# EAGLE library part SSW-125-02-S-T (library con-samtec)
THROUGH-HOLE .025" SQ POST SOCKET Source: Samtec SSW.pdf
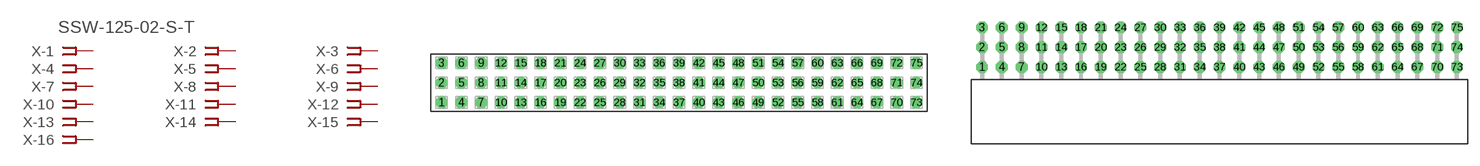
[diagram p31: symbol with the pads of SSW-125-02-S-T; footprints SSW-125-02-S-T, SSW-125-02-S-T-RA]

Designator prefix X; gates -1=FPINV -2=FPIN -3=FPIN -4=FPIN -5=FPIN -6=FPIN -7=FPIN -8=FPIN -9=FPIN -10=FPIN -11=FPIN -12=FPIN -13=FPIN -14=FPIN -15=FPIN -16=FPIN -17=FPIN -18=FPIN -19=FPIN -20=FPIN -21=FPIN -22=FPIN -23=FPIN -24=FPIN -25=FPIN -26=FPIN -27=FPIN -28=FPIN -29=FPIN -30=FPIN -31=FPIN -32=FPIN -33=FPIN -34=FPIN -35=FPIN -36=FPIN -37=FPIN -38=FPIN -39=FPIN -40=FPIN -41=FPIN -42=FPIN -43=FPIN -44=FPIN -45=FPIN -46=FPIN -47=FPIN -48=FPIN -49=FPIN -50=FPIN -51=FPIN -52=FPIN -53=FPIN -54=FPIN -55=FPIN -56=FPIN -57=FPIN -58=FPIN -59=FPIN -60=FPIN -61=FPIN -62=FPIN -63=FPIN -64=FPIN -65=FPIN -66=FPIN -67=FPIN -68=FPIN -69=FPIN -70=FPIN -71=FPIN -72=FPIN -73=FPIN -74=FPIN -75=FPIN

## SSW-125-02-S-T (MPN: SSW-125-02-S-T; OC_FARNELL: unknown; OC_NEWARK: 82P9300)  [SSW-125-02-S-T]
1  -1:1  pas
2  -2:1  pas
3  -3:1  pas
4  -4:1  pas
5  -5:1  pas
6  -6:1  pas
7  -7:1  pas
8  -8:1  pas
9  -9:1  pas
10  -10:1  pas
11  -11:1  pas
12  -12:1  pas
13  -13:1  pas
14  -14:1  pas
15  -15:1  pas
16  -16:1  pas
17  -17:1  pas
18  -18:1  pas
19  -19:1  pas
20  -20:1  pas
21  -21:1  pas
22  -22:1  pas
23  -23:1  pas
24  -24:1  pas
25  -25:1  pas
26  -26:1  pas
27  -27:1  pas
28  -28:1  pas
29  -29:1  pas
30  -30:1  pas
31  -31:1  pas
32  -32:1  pas
33  -33:1  pas
34  -34:1  pas
35  -35:1  pas
36  -36:1  pas
37  -37:1  pas
38  -38:1  pas
39  -39:1  pas
40  -40:1  pas
41  -41:1  pas
42  -42:1  pas
43  -43:1  pas
44  -44:1  pas
45  -45:1  pas
46  -46:1  pas
47  -47:1  pas
48  -48:1  pas
49  -49:1  pas
50  -50:1  pas
51  -51:1  pas
52  -52:1  pas
53  -53:1  pas
54  -54:1  pas
55  -55:1  pas
56  -56:1  pas
57  -57:1  pas
58  -58:1  pas
59  -59:1  pas
60  -60:1  pas
61  -61:1  pas
62  -62:1  pas
63  -63:1  pas
64  -64:1  pas
65  -65:1  pas
66  -66:1  pas
67  -67:1  pas
68  -68:1  pas
69  -69:1  pas
70  -70:1  pas
71  -71:1  pas
72  -72:1  pas
73  -73:1  pas
74  -74:1  pas
75  -75:1  pas

## SSW-125-02-S-TRA (MPN: SSW-125-02-S-T-RA; OC_FARNELL: unknown; OC_NEWARK: 82P9301)  [SSW-125-02-S-T-RA]
Pads as for SSW-125-02-S-T

## Footprint SSW-125-02-S-T (pad centres in mm)
THROUGH-HOLE .025" SQ POST SOCKET Source: Samtec SSW.pdf
drill 1 pad 1.5 octagon: 1 -30.48,-2.54; 2 -30.48,0; 3 -30.48,2.54; 4 -27.94,-2.54; 5 -27.94,0; 6 -27.94,2.54; 7 -25.4,-2.54; 8 -25.4,0; 9 -25.4,2.54; 10 -22.86,-2.54; 11 -22.86,0; 12 -22.86,2.54; 13 -20.32,-2.54; 14 -20.32,0; 15 -20.32,2.54; 16 -17.78,-2.54; 17 -17.78,0; 18 -17.78,2.54; 19 -15.24,-2.54; 20 -15.24,0; 21 -15.24,2.54; 22 -12.7,-2.54; 23 -12.7,0; 24 -12.7,2.54; 25 -10.16,-2.54; 26 -10.16,0; 27 -10.16,2.54; 28 -7.62,-2.54; 29 -7.62,0; 30 -7.62,2.54; 31 -5.08,-2.54; 32 -5.08,0; 33 -5.08,2.54; 34 -2.54,-2.54; 35 -2.54,0; 36 -2.54,2.54; 37 0,-2.54; 38 0,0; 39 0,2.54; 40 2.54,-2.54; 41 2.54,0; 42 2.54,2.54; 43 5.08,-2.54; 44 5.08,0; 45 5.08,2.54; 46 7.62,-2.54; 47 7.62,0; 48 7.62,2.54; 49 10.16,-2.54; 50 10.16,0; 51 10.16,2.54; 52 12.7,-2.54; 53 12.7,0; 54 12.7,2.54; 55 15.24,-2.54; 56 15.24,0; 57 15.24,2.54; 58 17.78,-2.54; 59 17.78,0; 60 17.78,2.54; 61 20.32,-2.54; 62 20.32,0; 63 20.32,2.54; 64 22.86,-2.54; 65 22.86,0; 66 22.86,2.54; 67 25.4,-2.54; 68 25.4,0; 69 25.4,2.54; 70 27.94,-2.54; 71 27.94,0; 72 27.94,2.54; 73 30.48,-2.54; 74 30.48,0; 75 30.48,2.54

## Footprint SSW-125-02-S-T-RA (pad centres in mm)
THROUGH-HOLE .025" SQ POST SOCKET Source: Samtec SSW.pdf
drill 1 pad 1.5 octagon: 1 -30.48,1.524; 2 -30.48,4.064; 3 -30.48,6.604; 4 -27.94,1.524; 5 -27.94,4.064; 6 -27.94,6.604; 7 -25.4,1.524; 8 -25.4,4.064; 9 -25.4,6.604; 10 -22.86,1.524; 11 -22.86,4.064; 12 -22.86,6.604; 13 -20.32,1.524; 14 -20.32,4.064; 15 -20.32,6.604; 16 -17.78,1.524; 17 -17.78,4.064; 18 -17.78,6.604; 19 -15.24,1.524; 20 -15.24,4.064; 21 -15.24,6.604; 22 -12.7,1.524; 23 -12.7,4.064; 24 -12.7,6.604; 25 -10.16,1.524; 26 -10.16,4.064; 27 -10.16,6.604; 28 -7.62,1.524; 29 -7.62,4.064; 30 -7.62,6.604; 31 -5.08,1.524; 32 -5.08,4.064; 33 -5.08,6.604; 34 -2.54,1.524; 35 -2.54,4.064; 36 -2.54,6.604; 37 0,1.524; 38 0,4.064; 39 0,6.604; 40 2.54,1.524; 41 2.54,4.064; 42 2.54,6.604; 43 5.08,1.524; 44 5.08,4.064; 45 5.08,6.604; 46 7.62,1.524; 47 7.62,4.064; 48 7.62,6.604; 49 10.16,1.524; 50 10.16,4.064; 51 10.16,6.604; 52 12.7,1.524; 53 12.7,4.064; 54 12.7,6.604; 55 15.24,1.524; 56 15.24,4.064; 57 15.24,6.604; 58 17.78,1.524; 59 17.78,4.064; 60 17.78,6.604; 61 20.32,1.524; 62 20.32,4.064; 63 20.32,6.604; 64 22.86,1.524; 65 22.86,4.064; 66 22.86,6.604; 67 25.4,1.524; 68 25.4,4.064; 69 25.4,6.604; 70 27.94,1.524; 71 27.94,4.064; 72 27.94,6.604; 73 30.48,1.524; 74 30.48,4.064; 75 30.48,6.604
